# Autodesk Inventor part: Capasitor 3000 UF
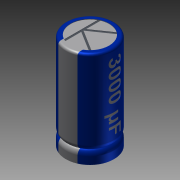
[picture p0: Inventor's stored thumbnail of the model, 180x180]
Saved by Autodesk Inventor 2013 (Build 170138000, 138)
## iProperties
Company: Autodesk Inc.
Created: 2005-12
Part Number: Capasitor 3000 UF
Document SubType Name: Modeling
Designer: Autodesk Inc.
Density: 1 g/cm^3
Mass: 1.55367 g
Surface Area: 7.94602 cm^2
Volume: 1.55367 cm^3
Material: Allgemein
Title: Personal Computer
Author: Autodesk Inc.
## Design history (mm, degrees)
sketch "Sketch1"
  geometry: L1 (0, 7)-(0, -7) reference; L2 (-7, 0)-(7, 0) reference; C1 r 5 at (0, 0)
  constraints: 2 midpoint, 1 centre point
  dimensions: "d0" = 10 diameter of C1
extrude "Extrusion1" new body sketch "Sketch1" distance "d1" = 20; taper "d2" = 0 deg
revolve "Revolution1" stored, may be unused: angle "d19" = 90 deg
sketch "Sketch2"
  geometry: C1 r 5 at (0, 0) reference; C2 r 4 at (0, 0)
  constraints: 1 centre point, 1 coincident
  dimensions: "d3" = 1 radial gap between concentric circles of C2 C1
extrude "Extrusion2" cut sketch "Sketch2" distance "d4" = 0.1; taper "d5" = 0 deg
sketch "Sketch3"
  geometry: L1 (-1.908, 3.716)-(-1.481, 3.716); L2 (-1.481, 3.716)-(-1.481, -3.863); L3 (-1.481, -3.863)-(-1.908, -3.863); L4 (-1.908, -3.863)-(-1.908, 3.716); L5 (-1.481, 0.128)-(-1.732, 0.489); L6 (-1.732, 0.489)-(2.523, 3.446); L7 (2.523, 3.446)-(2.773, 3.085); L8 (2.773, 3.085)-(-1.481, 0.128); L9 (-1.481, 0.128)-(-1.683, -0.197); L10 (-1.683, -0.197)-(2.995, -3.106); L11 (2.995, -3.106)-(3.197, -2.781); L12 (3.197, -2.781)-(-1.481, 0.128); 1 further point
  constraints: 24 end point, 6 parallel, 3 perpendicular, 1 horizontal, 1 point on line, 2 other
extrude "Extrusion3" cut sketch "Sketch3" distance "d6" = 0.05; taper "d7" = 0 deg
fillet "Fillet1" dims "d8" = 0.5
sketch "Sketch5"
  geometry: L1 (2, -3.464)-(2, -6); L2 (2, -6)-(-2, -6); L3 (-2, -6)-(-2, -3.464); L4 (0, -8.2)-(0, 7.2) reference; A1 r 4 centre (0, 0) between (-2, -3.464) and (2, -3.464) reference; 3 further points
  constraints: 6 end point, 2 point on circle, 1 coincident, 1 parallel, 1 point on line, 1 vertical alignment, 2 other
  dimensions: "d12" = 1 distance from line of L2 point (0, -5); "d13" = 4 distance of L1.end L2.end
split "Split1" sketch "Sketch5"
workplane "Work Plane1"
sketch "Sketch4"
  geometry: L1 (-18.536, 1.854)-(-2.927, 1.854); L2 (-2.927, 1.854)-(-2.927, -1.985); L3 (-2.927, -1.985)-(-18.536, -1.985); L4 (-18.536, -1.985)-(-18.536, 1.854)
  constraints: 2 other
emboss "Emboss1" sketch "Sketch4" dims "d10" = 0.05, "d11" = 0
body "Solid1"
sketch "Sketch6"
  geometry: L1 (0, 24)-(0, -4) reference; L2 (5, 0)-(5, 20) reference; L3 (5, 3.5)-(5, 1.5); L4 (5, 2.5)-(4.5, 2.5); L5 (-5, 0)-(5, 0) reference; A1 r 1.25 centre (3.75, 3.5) between (4.5, 2.5) and (5, 3.5); A2 r 1.25 centre (3.75, 1.5) between (5, 1.5) and (4.5, 2.5); 1 further point
  constraints: 4 end point, 4 point on circle, 2 centre point, 2 point on line, 2 tangent, 1 collinear, 1 horizontal, 1 midpoint
  dimensions: "d16" = 2 distance of L3.start L3.end; "d17" = 2.5 distance between parallel lines of L5 L4; "d18" = 0.5 distance of L4.start L4.end
